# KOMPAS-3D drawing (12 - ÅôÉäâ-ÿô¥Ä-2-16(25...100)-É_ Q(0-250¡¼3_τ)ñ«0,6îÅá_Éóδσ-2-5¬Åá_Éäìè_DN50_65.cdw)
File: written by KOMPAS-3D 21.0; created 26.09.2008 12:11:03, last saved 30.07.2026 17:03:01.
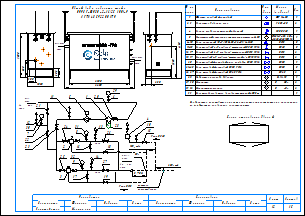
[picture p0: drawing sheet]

Sheets 1-2: A3, landscape

Document properties: Наименование: Макро:21; Автор: RaskoAdmin; Форматы листов документа: 2xA3; Полное имя файла: \\UR38nt01\Departments\КТО\КБ ПУРДГ\Заявки\Прайс-лист на типовые шкафы ГРПШ\ПУРДГ_стандарт_30_04_2026\ПУРДГ с РДНК\ПУРДГ-ШУЭО-2-16(25...100)-Р_ Q(0-250нм3_ч)до0,6МПа_Рвых-2-5кПа_РДНК_DN50_65.cdw

Title block, sheet 1: Наименование: Пункт учета газа / ПУГ-Ш-400-Р / ЛГТИ.485922.001ТУ; designation: ЛГТИ.03.4411141; sheet number: 1; Количество листов документа: 2; organisation: ООО "ЭЛЬСТЕР Газэлектроника"; Форматы листов документа: A3; stored path: C:\Рабочие документы\Компас\ПУГ\Схема.cdw; Разработал: Устинов; Проверил: Кошкин; Утвердил: Кошкин
Title block, sheet 2: sheet number: 2; stored path: D:\Рабочие документы\Заявки\ПУРДГ\ПУРДГ-ШУЭО-2-100-Р 4411220.cdw; designation, second copy: ЛГТИ.03.4411141-

Views: Вид 1, Вид 2
Referenced files: wcvoit.frw
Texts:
  Normal
  № на
  схеме
  Усл.
  обозн.
  Марка
  (модель)
  Кол.
  Фильтр газовый фланцевый
  ФГ 16-50
  Регулятор давления газа
  РДНК-50
  Клапан предохранительный сбросной
  КПС DN20
  Измерительный комплекс с ротационным счетчиком Ду50
  СГ-ЭК-Р-(0,2...2,0)-
  Кран кнопочный VE-РАСКО-НЗ-1,6-G1/2-М20
  DN15
  Кран шаровой "под приварку" штуцерный DN20 PN16
  DN20
  Кран шаровой "под приварку" штуцерный DN15 PN16
  Кран шаровой "под приварку" штуцерный п/п DN15 PN16
  Кран шаровой фланцевый с мех. приводом DN50 PN16
  Кран шаровой фланцевый DN50 PN16
  Кран шаровой фланцевый DN65 PN16
  DN50
  DN65
  Индикатор перепада давления
  Манометр
  Манометр-напоромер
  Электрообогреватель взрывозащищенный 400Вт
  Delta 15
  0...     МПа
  0...     кПа
  Общий вид и габариты шкафа
  ПУРДГ-ШУЭО-2-16(25...100)-Р
  Выход газа
  Вход газа
  logo-rasko-ge.png
  DN 1
  местное
  сопротивление
  Римп DN15
  Римп DN20
  Выход
  газа
  Р=     кПа
  Вход
  Р=       МПа
  PDI
  Схема открывания дверей
  Предприятие изготовитель может заменять комплектующие на аналогичные,
  не ухудшающие заявленных характеристик.
  Должность
  Конструктор
  Фамилия
  Подпись
  Дата
  Согласовано
  Максимкин
  Лист
  Листов
  POLYLINE_STYLE_0.18_RGB_0_0_0
  POLYLINE_STYLE_0.50_RGB_0_0_0
  POLYLINE_STYLE_0.34_RGB_0_0_0
  PHANTOM_RGB_0_0_0_SC_1_THICK_0.18
  K5LT_THIN_RGB_0_0_0_THICK_0.18
  K5LT32769_RGB_0_0_0_THICK_0.18
  K5LT12_RGB_0_0_0_SC_1_THICK_0.18
  K5LT_DASHED_RGB_0_0_0_SC_1_THICK_0.18
  ACISOTGL_RGB_0_0_0_SC_0.8_THICK_0.25
  CONTINUOUS_RGB_0_127_31_THICK_0.3
  CONTINUOUS_RGB_0_0_255_THICK_0.35
  CONTINUOUS_RGB_255_0_0_THICK_0.35
  POLYLINE_STYLE_0.25_RGB_0_0_0
  CONTINUOUS_RGB_0_0_0_THICK_0.5
  POLYLINE_STYLE_0.35_RGB_0_0_255
  CONTINUOUS_RGB_0_0_0_THICK_0.4
  CONTINUOUS_RGB_0_0_0_THICK_0.35
  НЕВИДИМАЯ_RGB_0_0_0_SC_0.3_THICK_0.25
  СONTINUOUS_RGB_0_0_0_THICK_0.25
  ОСЕВАЯ2_RGB_248_153_30_SC_0.3_THICK_0.25
  Без оформления
Dimensions and other numbers on the sheet: 1; 2, 3; 2; 4; 5; 6-10; 11-15; 16, 17; 18, 19; 20; 21-25; 26, 27; 28; 29, 30; 31, 32; 33; 1500; 250; 300; 1050; 550; 305; 2300; 4130; 2000; 2600; 5,,,7DN 1; 7; 30; 12; 21; 22; 23; 11; 6; 29; 24; 31; 8; 16; 13; 26; 18; 10; 15; 25; 32; 9; 3; 17; 14; 27; 19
